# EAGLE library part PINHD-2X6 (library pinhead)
PIN HEADER
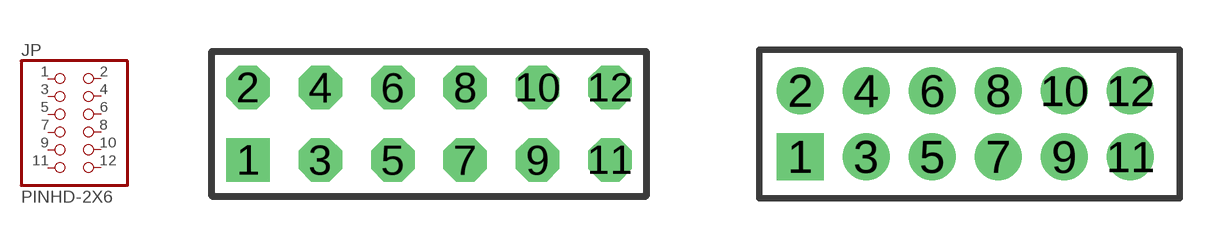
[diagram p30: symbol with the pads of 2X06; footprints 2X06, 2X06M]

Designator prefix JP

## PINHD-2X6  [2X06]
1  1  pas
2  2  pas
3  3  pas
4  4  pas
5  5  pas
6  6  pas
7  7  pas
8  8  pas
9  9  pas
10  10  pas
11  11  pas
12  12  pas

## PINHD-2X6M  [2X06M]
Pads as for 2X06

## Footprint 2X06 (pad centres in mm)
PIN HEADER - 0.1"
drill 1.016 square: 1 -6.35,-1.27
drill 1.016 octagon: 2 -6.35,1.27; 3 -3.81,-1.27; 4 -3.81,1.27; 5 -1.27,-1.27; 6 -1.27,1.27; 7 1.27,-1.27; 8 1.27,1.27; 9 3.81,-1.27; 10 3.81,1.27; 11 6.35,-1.27; 12 6.35,1.27

## Footprint 2X06M (pad centres in mm)
PIN HEADER - 2MM"
drill 0.914 square: 1 -5,-1
drill 0.914 round: 2 -5,1; 3 -3,-1; 4 -3,1; 5 -1,-1; 6 -1,1; 7 1,-1; 8 1,1; 9 3,-1; 10 3,1; 11 5,-1; 12 5,1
